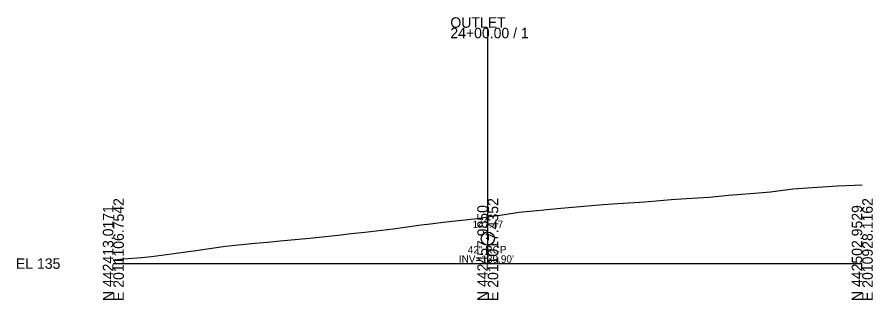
# Model space of a CAD drawing. Extents: x -26 to 1203, y -15 to 9526.
# Drawn here: x 974.3 to 1202.8, y 3990.3 to 4065.8 of the extents above; entities that cross this region are included whole.
import ezdxf

# ---------------------------------------------------------------- set-up
doc = ezdxf.new("R2010")
doc.units = 0
for name, color, linetype in [('Default', 7, 'Continuous'), ('Exist Cross Section Cell', 7, 'Continuous'), ('Exist XS Center Line Elevation Label', 7, 'Continuous'), ('Exist XS Ground Line', 7, 'Continuous'), ('Prop XSC Text', 7, 'Continuous')]:
    doc.layers.add(name, color=color, linetype=linetype)

msp = doc.modelspace()

# ---------------------------------------------------------------- linework, layer by layer
at = {"layer": 'Default'}
msp.add_line((1100, 4000), (1100, 4004.9), dxfattribs=at)
at = {"layer": 'Exist Cross Section Cell'}
for p, q in [((1100, 4000), (1100, 4062.97)), ((1000, 4000), (1100, 4000)), ((1100, 4000), (1200, 4000))]:
    msp.add_line(p, q, dxfattribs=at)
at = {"layer": 'Exist XS Ground Line'}
msp.add_lwpolyline([(1000, 4001.02), (1002.78, 4001.26), (1007.56, 4001.61), (1010.23, 4001.92), (1015.53, 4002.63), (1018.76, 4003.01), (1022.03, 4003.52), (1029.95, 4004.67), (1037.77, 4005.47), (1041.15, 4005.75), (1044.58, 4006.07), (1052.35, 4006.77), (1060, 4007.59), (1063.54, 4008.02), (1067.13, 4008.38), (1074.74, 4009.26), (1082.24, 4010.31), (1084.7, 4010.65), (1085.93, 4010.77), (1089.67, 4011.21), (1097.13, 4012.06), (1100, 4012.47), (1104.48, 4013.09), (1108.32, 4013.73), (1112.22, 4014.07), (1119.52, 4014.78), (1126.72, 4015.41), (1130.72, 4015.81), (1134.77, 4016.03), (1141.91, 4016.47), (1148.96, 4017.1), (1151.72, 4017.32), (1153.11, 4017.41), (1159.16, 4017.74), (1164.3, 4018.3), (1166.61, 4018.47), (1171.2, 4018.78), (1175.5, 4019.14), (1181.5, 4020), (1186.7, 4020.36), (1193.43, 4020.77), (1197.89, 4020.93), (1200, 4020.99)], dxfattribs=at)
at = {"layer": 'Prop XSC Text'}
msp.add_circle((1100, 4006.65), 1.75, dxfattribs=at)

# ---------------------------------------------------------------- texts
at = {"layer": 'Exist Cross Section Cell'}
for s, p in [('OUTLET', (1090, 4062.97)), ('24+00.00 / 1', (1090, 4060.17)), ('EL 135', (974, 3998.6))]:
    msp.add_text(s, height=2.8, dxfattribs=at).set_placement(p)
for s, p in [('N 442413.0171', (1000, 3990)), ('E 2011106.7542', (1002.8, 3990)), ('N 442457.9850', (1100, 3990)), ('E 2011017.4352', (1102.8, 3990)), ('N 442502.9529', (1200, 3990)), ('E 2010928.1162', (1202.8, 3990))]:
    msp.add_text(s, height=2.8, rotation=90, dxfattribs=at).set_placement(p)
at = {"layer": 'Exist XS Center Line Elevation Label'}
msp.add_text('147.47', height=2, dxfattribs=at).set_placement((1095.94, 4009.47))
at = {"layer": 'Prop XSC Text'}
for s, p in [('42" RCP', (1094.67, 4002.72)), ("INV=139.90'", (1092.26, 4000.22))]:
    msp.add_text(s, height=2, dxfattribs=at).set_placement(p)

doc.saveas('drawing.dxf')
